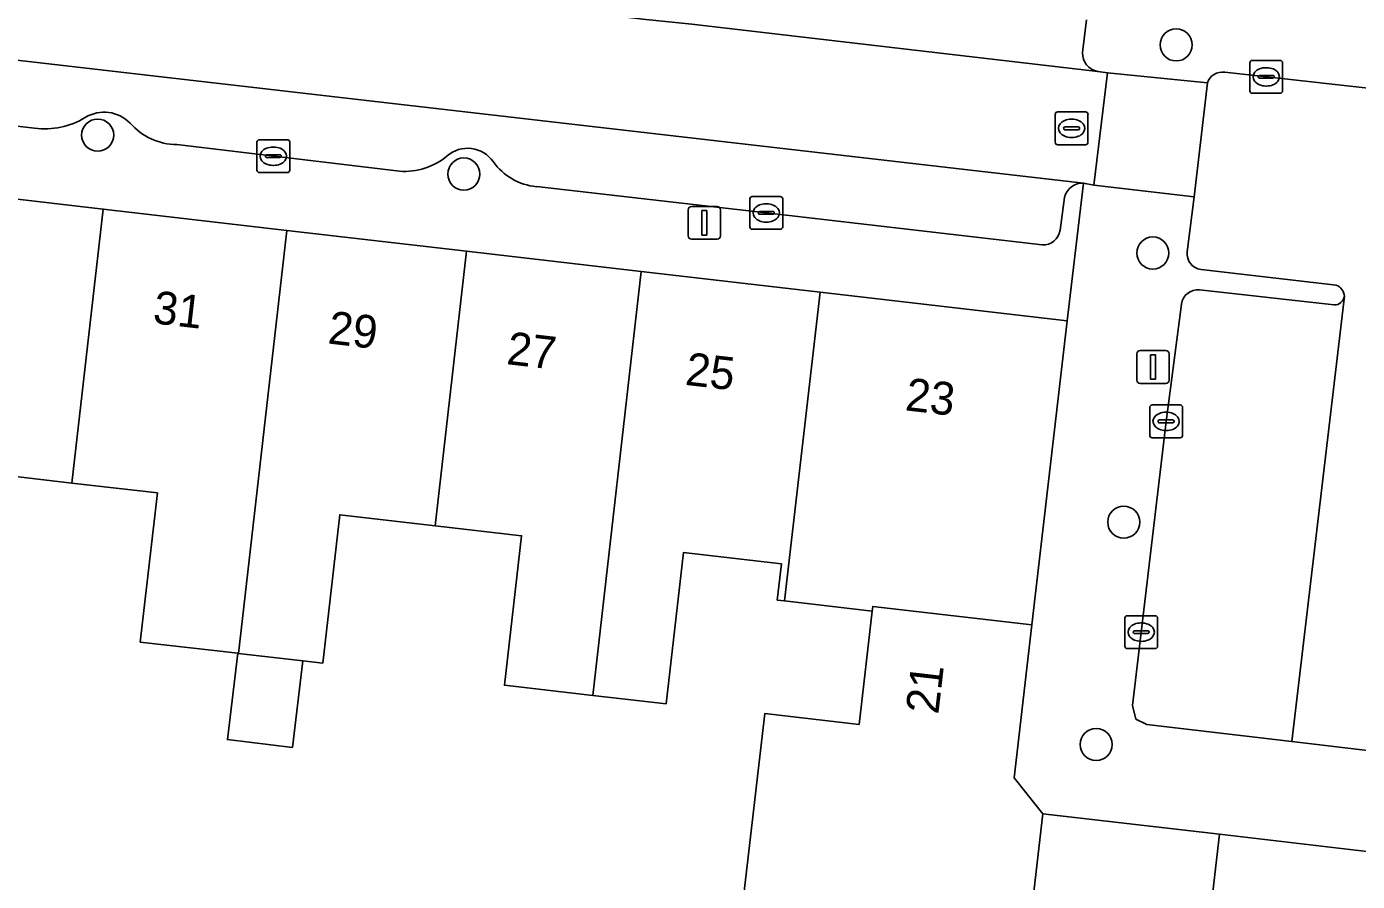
# Model space of a CAD drawing. Extents: x 161692 to 162379, y 380760 to 381678.
# Drawn here: x 161926.1 to 161966.68, y 381373.54 to 381399.59 of the extents above; entities that cross this region are included whole.
import ezdxf

# ---------------------------------------------------------------- set-up
doc = ezdxf.new("R2010")
doc.units = 0
for name, color, linetype in [('IMGEO_Boom', 7, 'Continuous'), ('IMGEO_Erf', 7, 'Continuous'), ('IMGEO_Kolk', 7, 'Continuous'), ('IMGEO_Lichtmast', 7, 'Continuous'), ('IMGEO_Pand', 7, 'Continuous'), ('IMGEO_Pand_nummerreeks', 7, 'Continuous'), ('IMGEO_Parkeervlak_open', 7, 'Continuous'), ('IMGEO_Rijbaan_lokaal_open', 7, 'Continuous'), ('IMGEO_Rioolput', 7, 'Continuous'), ('IMGEO_Voetpad_open', 7, 'Continuous')]:
    doc.layers.add(name, color=color, linetype=linetype)

msp = doc.modelspace()

# ---------------------------------------------------------------- linework, layer by layer
at = {"layer": 'IMGEO_Boom'}
for centre in [(161961.154, 381399.031), (161928.263, 381396.283), (161939.431, 381395.096), (161960.442, 381392.689), (161959.553, 381384.486), (161958.712, 381377.712)]:
    msp.add_circle(centre, 0.489, dxfattribs=at)
at = {"layer": 'IMGEO_Erf'}
msp.add_lwpolyline([(161947.636, 381370.269), (161948.606, 381378.655), (161951.482, 381378.323), (161951.882, 381381.775), (161949.208, 381382.085), (161948.988, 381382.11), (161949.116, 381383.222), (161946.131, 381383.567), (161945.596, 381378.948), (161943.36, 381379.207), (161940.667, 381379.519), (161941.193, 381384.071), (161938.557, 381384.376), (161935.648, 381384.713), (161935.125, 381380.191), (161934.52, 381380.262), (161934.204, 381377.624), (161932.219, 381377.862), (161932.535, 381380.491), (161929.56, 381380.835), (161930.086, 381385.377), (161927.478, 381385.678), (161924.635, 381386.007)], dxfattribs=at)
at = {"layer": 'IMGEO_Kolk'}
for p, q in [((161963.399, 381397.631), (161963.399, 381398.483)), ((161963.474, 381398.557), (161964.326, 381398.557)), ((161964.4, 381398.483), (161964.4, 381397.631)), ((161963.658, 381398.051), (161963.658, 381398.063)), ((161964.096, 381398.014), (161963.698, 381398.014)), ((161963.701, 381398.1), (161964.099, 381398.1)), ((161963.887, 381398.337), (161963.912, 381398.337)), ((161964.142, 381398.063), (161964.142, 381398.051)), ((161964.326, 381397.557), (161963.474, 381397.557)), ((161963.91, 381397.777), (161963.885, 381397.777)), ((161933.12, 381395.213), (161933.12, 381396.065)), ((161933.195, 381396.139), (161934.047, 381396.139)), ((161933.608, 381395.919), (161933.633, 381395.919)), ((161934.121, 381396.065), (161934.121, 381395.213)), ((161933.379, 381395.633), (161933.379, 381395.645)), ((161933.817, 381395.596), (161933.419, 381395.596)), ((161933.422, 381395.682), (161933.82, 381395.682)), ((161933.863, 381395.645), (161933.863, 381395.633)), ((161934.047, 381395.139), (161933.195, 381395.139)), ((161933.631, 381395.359), (161933.606, 381395.359)), ((161948.152, 381393.485), (161948.152, 381394.337)), ((161948.227, 381394.411), (161949.079, 381394.411)), ((161949.153, 381394.337), (161949.153, 381393.485)), ((161948.411, 381393.905), (161948.411, 381393.917)), ((161948.454, 381393.954), (161948.852, 381393.954)), ((161948.64, 381394.191), (161948.665, 381394.191)), ((161948.895, 381393.917), (161948.895, 381393.905)), ((161948.849, 381393.868), (161948.451, 381393.868)), ((161948.663, 381393.631), (161948.638, 381393.631)), ((161949.079, 381393.411), (161948.227, 381393.411)), ((161960.346, 381387.133), (161960.346, 381387.985)), ((161960.421, 381388.059), (161961.273, 381388.059)), ((161960.834, 381387.839), (161960.859, 381387.839)), ((161961.347, 381387.985), (161961.347, 381387.133)), ((161960.605, 381387.553), (161960.605, 381387.565)), ((161961.043, 381387.516), (161960.645, 381387.516)), ((161960.648, 381387.602), (161961.046, 381387.602)), ((161961.089, 381387.565), (161961.089, 381387.553)), ((161961.273, 381387.059), (161960.421, 381387.059)), ((161960.857, 381387.279), (161960.832, 381387.279)), ((161959.587, 381380.709), (161959.587, 381381.561)), ((161959.662, 381381.635), (161960.514, 381381.635)), ((161960.075, 381381.415), (161960.1, 381381.415)), ((161960.588, 381381.561), (161960.588, 381380.709)), ((161959.846, 381381.129), (161959.846, 381381.141)), ((161960.284, 381381.092), (161959.886, 381381.092)), ((161959.889, 381381.178), (161960.287, 381381.178)), ((161960.33, 381381.141), (161960.33, 381381.129)), ((161960.514, 381380.635), (161959.662, 381380.635)), ((161960.098, 381380.855), (161960.073, 381380.855))]:
    msp.add_line(p, q, dxfattribs=at)
for points in [[(161963.399, 381397.631), (161963.399, 381398.483)], [(161963.474, 381398.557), (161964.326, 381398.557)], [(161964.4, 381398.483), (161964.4, 381397.631)], [(161964.326, 381397.557), (161963.474, 381397.557)], [(161933.12, 381395.213), (161933.12, 381396.065)], [(161933.195, 381396.139), (161934.047, 381396.139)], [(161934.121, 381396.065), (161934.121, 381395.213)], [(161934.047, 381395.139), (161933.195, 381395.139)], [(161948.152, 381393.485), (161948.152, 381394.337)], [(161948.227, 381394.411), (161949.079, 381394.411)], [(161949.153, 381394.337), (161949.153, 381393.485)], [(161949.079, 381393.411), (161948.227, 381393.411)], [(161960.346, 381387.133), (161960.346, 381387.985)], [(161960.421, 381388.059), (161961.273, 381388.059)], [(161961.347, 381387.985), (161961.347, 381387.133)], [(161961.273, 381387.059), (161960.421, 381387.059)], [(161959.587, 381380.709), (161959.587, 381381.561)], [(161959.662, 381381.635), (161960.514, 381381.635)], [(161960.588, 381381.561), (161960.588, 381380.709)], [(161960.514, 381380.635), (161959.662, 381380.635)]]:
    msp.add_lwpolyline(points, dxfattribs=at)
for centre, radius, start, end in [((161963.476, 381398.481), 0.0765, 91.552, 178.448), ((161963.476, 381398.481), 0.0765, 91.552, 178.448), ((161964.324, 381398.481), 0.0765, 1.552, 88.448), ((161964.324, 381398.481), 0.0765, 1.552, 88.448), ((161963.698, 381398.06), 0.0403, 85.8775, 175.7526), ((161963.695, 381398.05), 0.0366, 178.938, 274.7102), ((161964.099, 381398.057), 0.043, 264.8664, 352.4533), ((161964.103, 381398.062), 0.0386, 1.7309, 96.639), ((161963.476, 381397.633), 0.0765, 181.552, 268.448), ((161963.476, 381397.633), 0.0765, 181.552, 268.448), ((161964.324, 381397.633), 0.0765, 271.552, 358.448), ((161964.324, 381397.633), 0.0765, 271.552, 358.448), ((161933.197, 381396.063), 0.0765, 91.552, 178.448), ((161933.197, 381396.063), 0.0765, 91.552, 178.448), ((161934.045, 381396.063), 0.0765, 1.552, 88.448), ((161934.045, 381396.063), 0.0765, 1.552, 88.448), ((161933.419, 381395.642), 0.0403, 85.8775, 175.7526), ((161933.416, 381395.632), 0.0366, 178.938, 274.7102), ((161933.82, 381395.639), 0.043, 264.8664, 352.4533), ((161933.824, 381395.644), 0.0386, 1.7309, 96.639), ((161933.197, 381395.215), 0.0765, 181.552, 268.448), ((161933.197, 381395.215), 0.0765, 181.552, 268.448), ((161934.045, 381395.215), 0.0765, 271.552, 358.448), ((161934.045, 381395.215), 0.0765, 271.552, 358.448), ((161948.229, 381394.335), 0.0765, 91.552, 178.448), ((161948.229, 381394.335), 0.0765, 91.552, 178.448), ((161949.077, 381394.335), 0.0765, 1.552, 88.448), ((161949.077, 381394.335), 0.0765, 1.552, 88.448), ((161948.451, 381393.914), 0.0403, 85.8775, 175.7526), ((161948.448, 381393.904), 0.0366, 178.938, 274.7102), ((161948.852, 381393.911), 0.043, 264.8664, 352.4533), ((161948.856, 381393.916), 0.0386, 1.7309, 96.639), ((161948.229, 381393.487), 0.0765, 181.552, 268.448), ((161948.229, 381393.487), 0.0765, 181.552, 268.448), ((161949.077, 381393.487), 0.0765, 271.552, 358.448), ((161949.077, 381393.487), 0.0765, 271.552, 358.448), ((161960.423, 381387.983), 0.0765, 91.552, 178.448), ((161960.423, 381387.983), 0.0765, 91.552, 178.448), ((161961.271, 381387.983), 0.0765, 1.552, 88.448), ((161961.271, 381387.983), 0.0765, 1.552, 88.448), ((161960.645, 381387.562), 0.0403, 85.8775, 175.7526), ((161960.642, 381387.552), 0.0366, 178.938, 274.7102), ((161961.046, 381387.559), 0.043, 264.8664, 352.4533), ((161961.05, 381387.564), 0.0386, 1.7309, 96.639), ((161960.423, 381387.135), 0.0765, 181.552, 268.448), ((161960.423, 381387.135), 0.0765, 181.552, 268.448), ((161961.271, 381387.135), 0.0765, 271.552, 358.448), ((161961.271, 381387.135), 0.0765, 271.552, 358.448), ((161959.664, 381381.559), 0.0765, 91.552, 178.448), ((161959.664, 381381.559), 0.0765, 91.552, 178.448), ((161960.512, 381381.559), 0.0765, 1.552, 88.448), ((161960.512, 381381.559), 0.0765, 1.552, 88.448), ((161959.886, 381381.138), 0.0403, 85.8775, 175.7526), ((161959.883, 381381.128), 0.0366, 178.938, 274.7102), ((161960.287, 381381.135), 0.043, 264.8664, 352.4533), ((161960.291, 381381.14), 0.0386, 1.7309, 96.639), ((161959.664, 381380.711), 0.0765, 181.552, 268.448), ((161959.664, 381380.711), 0.0765, 181.552, 268.448), ((161960.512, 381380.711), 0.0765, 271.552, 358.448), ((161960.512, 381380.711), 0.0765, 271.552, 358.448)]:
    msp.add_arc(centre, radius, start, end, dxfattribs=at)
for centre, major_axis, ratio, start_param, end_param in [((161963.886, 381398.057), (-0.387, 0.002), 0.722429, 4.712389, 7.853982), ((161963.911, 381398.057), (-0.39, 0.002), 0.717154, 1.570796, 4.712389), ((161933.607, 381395.639), (-0.387, 0.002), 0.722429, 4.712389, 7.853982), ((161933.632, 381395.639), (-0.39, 0.002), 0.717154, 1.570796, 4.712389), ((161948.639, 381393.911), (-0.387, 0.002), 0.722429, 4.712389, 7.853982), ((161948.664, 381393.911), (-0.39, 0.002), 0.717154, 1.570796, 4.712389), ((161960.833, 381387.559), (-0.387, 0.002), 0.722429, 4.712389, 7.853982), ((161960.858, 381387.559), (-0.39, 0.002), 0.717154, 1.570796, 4.712389), ((161960.074, 381381.135), (-0.387, 0.002), 0.722429, 4.712389, 7.853982), ((161960.099, 381381.135), (-0.39, 0.002), 0.717154, 1.570796, 4.712389)]:
    msp.add_ellipse(centre, major_axis=major_axis, ratio=ratio, start_param=start_param, end_param=end_param, dxfattribs=at)
at = {"layer": 'IMGEO_Lichtmast'}
for p, q in [((161946.269, 381393.209), (161946.269, 381394.009)), ((161946.269, 381394.009), (161946.269, 381393.209)), ((161946.369, 381394.109), (161947.159, 381394.109)), ((161947.159, 381394.109), (161946.369, 381394.109)), ((161947.259, 381394.009), (161947.259, 381393.209)), ((161947.259, 381393.209), (161947.259, 381394.009)), ((161947.159, 381393.109), (161946.369, 381393.109)), ((161946.369, 381393.109), (161947.159, 381393.109)), ((161959.951, 381388.816), (161959.951, 381389.616)), ((161959.951, 381389.616), (161959.951, 381388.816)), ((161960.051, 381389.716), (161960.841, 381389.716)), ((161960.841, 381389.716), (161960.051, 381389.716)), ((161960.941, 381389.616), (161960.941, 381388.816)), ((161960.941, 381388.816), (161960.941, 381389.616)), ((161960.841, 381388.716), (161960.051, 381388.716)), ((161960.051, 381388.716), (161960.841, 381388.716))]:
    msp.add_line(p, q, dxfattribs=at)
for points in [[(161946.689, 381393.984), (161946.839, 381393.984), (161946.839, 381393.234), (161946.689, 381393.234), (161946.689, 381393.984)], [(161960.371, 381389.591), (161960.521, 381389.591), (161960.521, 381388.841), (161960.371, 381388.841), (161960.371, 381389.591)]]:
    msp.add_lwpolyline(points, dxfattribs=at)
for centre, start, end in [((161946.369, 381394.009), 90, 180), ((161946.369, 381394.009), 90, 180), ((161947.159, 381394.009), 0, 90), ((161947.159, 381394.009), 360, 90), ((161946.369, 381393.209), 180, 270), ((161946.369, 381393.209), 180, 270), ((161947.159, 381393.209), 270, 0), ((161947.159, 381393.209), 270, 0), ((161960.051, 381389.616), 90, 180), ((161960.051, 381389.616), 90, 180), ((161960.841, 381389.616), 0, 90), ((161960.841, 381389.616), 360, 90), ((161960.051, 381388.816), 180, 270), ((161960.051, 381388.816), 180, 270), ((161960.841, 381388.816), 270, 0), ((161960.841, 381388.816), 270, 0)]:
    msp.add_arc(centre, 0.1, start, end, dxfattribs=at)
at = {"layer": 'IMGEO_Pand'}
for points in [[(161921.631, 381381.698), (161924.103, 381381.412), (161924.635, 381386.007), (161927.478, 381385.678), (161928.431, 381394.026), (161923.109, 381394.642)], [(161934.034, 381393.378), (161928.431, 381394.026), (161927.478, 381385.678), (161930.086, 381385.377), (161929.56, 381380.835), (161932.535, 381380.491), (161932.562, 381380.488)], [(161939.512, 381392.744), (161934.034, 381393.378), (161932.562, 381380.488), (161934.52, 381380.262), (161935.125, 381380.191), (161935.648, 381384.713), (161938.557, 381384.376)], [(161938.557, 381384.376), (161941.193, 381384.071), (161940.667, 381379.519), (161943.36, 381379.207), (161944.835, 381392.128), (161939.512, 381392.744)], [(161950.299, 381391.496), (161944.835, 381392.128), (161943.36, 381379.207), (161945.596, 381378.948), (161946.131, 381383.567), (161949.116, 381383.222), (161948.988, 381382.11), (161949.208, 381382.085)], [(161951.882, 381381.775), (161951.899, 381381.918), (161956.754, 381381.363), (161957.825, 381390.625), (161950.299, 381391.496), (161949.208, 381382.085)], [(161957.087, 381375.598), (161956.922, 381375.806), (161956.214, 381376.699), (161956.754, 381381.363), (161951.899, 381381.918), (161951.882, 381381.775), (161951.482, 381378.323), (161948.606, 381378.655), (161947.636, 381370.269), (161946.875, 381363.696), (161955.334, 381362.684), (161955.684, 381365.713), (161955.874, 381367.252), (161956.116, 381367.224), (161956.343, 381369.182)], [(161934.52, 381380.262), (161932.562, 381380.488), (161932.535, 381380.491), (161932.219, 381377.862), (161934.204, 381377.624)], [(161957.087, 381375.598), (161956.343, 381369.182), (161956.116, 381367.224), (161958.683, 381366.927), (161958.167, 381362.467), (161960.986, 381362.141), (161962.474, 381374.974)], [(161966.028, 381358.452), (161966.898, 381365.98), (161967.292, 381369.384), (161967.867, 381374.35), (161966.617, 381374.495), (161962.474, 381374.974), (161960.986, 381362.141), (161960.632, 381359.076)]]:
    msp.add_lwpolyline(points, close=True, dxfattribs=at)
at = {"layer": 'IMGEO_Parkeervlak_open'}
for points in [[(161958.329, 381394.82), (161905.689, 381400.892)], [(161946.38, 381399.658), (161958.764, 381398.225)], [(161958.301, 381398.795), (161958.421, 381399.794)], [(161908.834, 381398.479), (161917.052, 381397.552), (161926.337, 381396.497)], [(161930.675, 381395.991), (161937.472, 381395.182)], [(161941.643, 381394.711), (161948.653, 381393.912), (161957.069, 381392.936)], [(161957.612, 381393.381), (161957.749, 381394.385)], [(161965.967, 381391.105), (161961.861, 381391.566)], [(161961.316, 381391.13), (161960.848, 381387.558), (161959.825, 381378.901), (161959.927, 381378.486), (161960.261, 381378.326), (161964.678, 381377.805), (161966.282, 381391.374)]]:
    msp.add_lwpolyline(points, dxfattribs=at)
for centre, radius, start, end in [((161958.842, 381398.761), 0.542, 176.4498, 261.7228), ((161926.669, 381398.779), 2.306, 261.7109, 301.7487), ((161928.46, 381395.869), 1.111, 44.2367, 121.3182), ((161930.706, 381397.928), 1.937, 221.5087, 269.0691), ((161937.624, 381397.203), 2.026, 265.7098, 309.8512), ((161939.546, 381394.928), 0.952, 34.9907, 130.9602), ((161941.812, 381396.522), 1.819, 215.1764, 264.6522), ((161958.312, 381394.239), 0.582, 88.3109, 165.4289), ((161957.094, 381393.459), 0.524, 267.2573, 351.4134), ((161961.809, 381391.072), 0.496, 83.9911, 173.3285), ((161965.975, 381391.415), 0.31, 268.5217, 352.4709)]:
    msp.add_arc(centre, radius, start, end, dxfattribs=at)
at = {"layer": 'IMGEO_Rijbaan_lokaal_open'}
for points in [[(161939.691, 381400.432), (161939.582, 381400.445), (161927.033, 381401.906), (161926.899, 381401.922), (161921.632, 381402.504), (161906.162, 381404.303), (161905.689, 381400.892), (161958.329, 381394.82), (161958.645, 381394.759), (161959.058, 381398.181), (161958.764, 381398.225), (161946.38, 381399.658), (161944.976, 381399.801)], [(161959.058, 381398.181), (161958.645, 381394.759), (161961.697, 381394.405), (161962.105, 381397.874)]]:
    msp.add_lwpolyline(points, close=True, dxfattribs=at)
for points in [[(161974.1, 381396.922), (161962.637, 381398.197)], [(161962.105, 381397.874), (161961.697, 381394.405), (161961.49, 381392.723)], [(161961.912, 381392.184), (161966.034, 381391.712)], [(161966.282, 381391.374), (161964.678, 381377.805), (161967.839, 381377.43), (161972.347, 381376.951), (161979.182, 381376.164), (161980.132, 381376.058), (161980.757, 381381.162), (161976.103, 381381.703)]]:
    msp.add_lwpolyline(points, dxfattribs=at)
for centre, radius, start, end in [((161962.559, 381397.726), 0.477, 80.5915, 161.936), ((161961.973, 381392.667), 0.487, 173.3591, 262.7579), ((161965.895, 381391.35), 0.387, 3.51, 69.0271)]:
    msp.add_arc(centre, radius, start, end, dxfattribs=at)
at = {"layer": 'IMGEO_Rioolput'}
for p, q in [((161957.463, 381396.062), (161957.463, 381396.914)), ((161957.538, 381396.988), (161958.39, 381396.988)), ((161957.951, 381396.768), (161957.976, 381396.768)), ((161958.464, 381396.914), (161958.464, 381396.062)), ((161957.722, 381396.482), (161957.722, 381396.494)), ((161958.16, 381396.445), (161957.762, 381396.445)), ((161957.765, 381396.531), (161958.163, 381396.531)), ((161958.206, 381396.494), (161958.206, 381396.482)), ((161958.39, 381395.988), (161957.538, 381395.988)), ((161957.974, 381396.208), (161957.949, 381396.208))]:
    msp.add_line(p, q, dxfattribs=at)
for points in [[(161957.463, 381396.062), (161957.463, 381396.914)], [(161957.538, 381396.988), (161958.39, 381396.988)], [(161958.464, 381396.914), (161958.464, 381396.062)], [(161958.39, 381395.988), (161957.538, 381395.988)]]:
    msp.add_lwpolyline(points, dxfattribs=at)
for centre, radius, start, end in [((161957.54, 381396.912), 0.0765, 91.552, 178.448), ((161957.54, 381396.912), 0.0765, 91.552, 178.448), ((161958.388, 381396.912), 0.0765, 1.552, 88.448), ((161958.388, 381396.912), 0.0765, 1.552, 88.448), ((161957.762, 381396.491), 0.0403, 85.8775, 175.7526), ((161957.759, 381396.481), 0.0366, 178.938, 274.7102), ((161958.163, 381396.488), 0.043, 264.8664, 352.4533), ((161958.167, 381396.493), 0.0386, 1.7309, 96.639), ((161957.54, 381396.064), 0.0765, 181.552, 268.448), ((161957.54, 381396.064), 0.0765, 181.552, 268.448), ((161958.388, 381396.064), 0.0765, 271.552, 358.448), ((161958.388, 381396.064), 0.0765, 271.552, 358.448)]:
    msp.add_arc(centre, radius, start, end, dxfattribs=at)
for centre, major_axis, ratio, start_param, end_param in [((161957.95, 381396.488), (-0.387, 0.002), 0.722429, 4.712389, 7.853982), ((161957.975, 381396.488), (-0.39, 0.002), 0.717154, 1.570796, 4.712389)]:
    msp.add_ellipse(centre, major_axis=major_axis, ratio=ratio, start_param=start_param, end_param=end_param, dxfattribs=at)
at = {"layer": 'IMGEO_Voetpad_open'}
for points in [[(161868.173, 381400.998), (161873.848, 381400.341), (161879.311, 381399.709), (161884.738, 381399.081), (161890.196, 381398.45), (161895.764, 381397.806), (161901.175, 381397.18), (161906.612, 381396.55), (161912.282, 381395.894), (161917.607, 381395.278), (161923.109, 381394.642), (161928.431, 381394.026), (161934.034, 381393.378), (161939.512, 381392.744), (161944.835, 381392.128), (161950.299, 381391.496), (161957.825, 381390.625), (161958.329, 381394.82)], [(161958.421, 381399.794), (161958.301, 381398.795)], [(161926.337, 381396.497), (161917.052, 381397.552), (161908.834, 381398.479)], [(161958.764, 381398.225), (161959.058, 381398.181), (161962.105, 381397.874)], [(161962.637, 381398.197), (161974.1, 381396.922)], [(161937.472, 381395.182), (161930.675, 381395.991)], [(161957.069, 381392.936), (161948.653, 381393.912), (161941.643, 381394.711)], [(161961.49, 381392.723), (161961.697, 381394.405), (161958.645, 381394.759), (161958.329, 381394.82), (161957.825, 381390.625), (161956.754, 381381.363), (161956.214, 381376.699), (161956.922, 381375.806), (161957.087, 381375.598), (161962.474, 381374.974), (161966.617, 381374.495), (161967.867, 381374.35)], [(161957.749, 381394.385), (161957.612, 381393.381)], [(161966.034, 381391.712), (161961.912, 381392.184)], [(161961.861, 381391.566), (161965.967, 381391.105)], [(161983.186, 381374.016), (161980.747, 381375.961), (161980.132, 381376.058), (161979.182, 381376.164), (161972.347, 381376.951), (161972.317, 381376.479), (161967.786, 381376.993), (161967.839, 381377.43), (161964.678, 381377.805), (161960.261, 381378.326), (161959.927, 381378.486), (161959.825, 381378.901), (161960.848, 381387.558), (161961.316, 381391.13)]]:
    msp.add_lwpolyline(points, dxfattribs=at)
for centre, radius, start, end in [((161958.842, 381398.761), 0.542, 176.4498, 261.7228), ((161962.559, 381397.726), 0.477, 80.5915, 161.936), ((161926.669, 381398.779), 2.306, 261.7109, 301.7487), ((161928.46, 381395.869), 1.111, 44.2367, 121.3182), ((161930.706, 381397.928), 1.937, 221.5087, 269.0691), ((161937.624, 381397.203), 2.026, 265.7098, 309.8512), ((161939.546, 381394.928), 0.952, 34.9907, 130.9602), ((161941.812, 381396.522), 1.819, 215.1764, 264.6522), ((161958.312, 381394.239), 0.582, 88.3109, 165.4289), ((161957.094, 381393.459), 0.524, 267.2573, 351.4134), ((161961.973, 381392.667), 0.487, 173.3591, 262.7579), ((161961.809, 381391.072), 0.496, 83.9911, 173.3285), ((161965.895, 381391.35), 0.387, 3.51, 69.0271), ((161965.975, 381391.415), 0.31, 268.5217, 352.4709)]:
    msp.add_arc(centre, radius, start, end, dxfattribs=at)

# ---------------------------------------------------------------- texts
at = {"layer": 'IMGEO_Pand_nummerreeks'}
for s, rotation, p in [('31', 353.3995, (161929.922, 381390.552)), ('29', 353.3995, (161935.258, 381389.935)), ('27', 353.4003, (161940.706, 381389.305)), ('25', 353.4003, (161946.154, 381388.674)), ('23', 353.4001, (161952.864, 381387.898)), ('21', 83.4112, (161953.898, 381378.612))]:
    msp.add_text(s, height=1, rotation=rotation, dxfattribs=at).set_placement(p)

doc.saveas('drawing.dxf')
